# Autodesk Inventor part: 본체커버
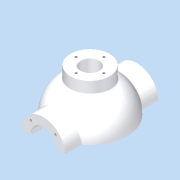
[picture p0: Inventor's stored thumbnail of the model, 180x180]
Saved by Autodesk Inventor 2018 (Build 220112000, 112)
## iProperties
Created: 2015-12
Part Number: 본체커버
Material: 알루미늄 6061
Document SubType Name: Modeling
Designer: mduedu
Density: 2.71 g/cm^3
Mass: 487.453 g
Surface Area: 431.319 cm^2
Volume: 179.872 cm^3
Appearance: 알루미늄 - 평지
Author: mduedu
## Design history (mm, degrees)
sketch "스케치1"
  geometry: L1 (-53, 0)-(53, 0); A1 r 53 centre (0, 0) between (53, 0) and (-53, 0); 2 further points
  constraints: 2 coincident, 2 end point, 2 point on circle, 1 centre point, 1 horizontal, 1 midpoint
  dimensions: "d0" = 53 radius of A1
revolve "회전1" sketch "스케치1" stored, may be unused: angle "d2" = 90 deg
feature "쉘1" dims "d11" = 8
node "작업 평면1"
sketch "스케치2"
  geometry: C1 r 31 at (0, 0); 1 further point
  constraints: 1 centre point, 1 coincident
  dimensions: "d4" = 62 diameter of C1
extrude "돌출1" join sketch "스케치2" stored distance "d5" = 10; taper "d6" = 0 deg
hole "구멍1" diameter "d14" = 35; stored, may be unused: countersink angle "d18" = 90 deg, drill point angle "d20" = 0 deg; dims "d12" = 10, "d13" = 10, "d15" = 6, "d16" = 4, "d17" = 2, "d19" = 16
hole "구멍2" diameter "d23" = 27; stored, may be unused: countersink angle "d27" = 90 deg, drill point angle "d29" = 0 deg; dims "d21" = 10, "d22" = 10, "d24" = 6, "d25" = 4, "d26" = 2, "d28" = 16
fillet "모깎기1" dims "d30" = 0.3
chamfer "모따기1" distance "d40" = 1; stored, may be unused: second distance "d41" = 2, angle "d42" = 45 deg
sketch "스케치4"
  geometry: L1 (0, 0)-(0, -25); L2 (0, 0)-(-17.678, -17.678); A1 r 25 centre (0, 0) between (-17.678, -17.678) and (0, -25); 1 further point
  constraints: 4 end point, 2 point on circle, 1 centre point, 1 coincident, 1 vertical
  dimensions: "d43" = 50 diameter of A1; "d47" = 45 deg angle of L1 L2
hole "구멍4" sketch "스케치4" at (-17.678, -17.678) diameter "d49" = 3.242; stored, may be unused: countersink angle "d53" = 90 deg, drill point angle "d55" = 118 deg; dims "d50" = 11, "d51" = 4, "d52" = 2, "d54" = 13
node "작업 평면3"
sketch "스케치6"
  geometry: C1 r 65 at (0, 0); 1 further point
  constraints: 1 centre point, 1 coincident
  dimensions: "d78" = 130 diameter of C1
extrude "돌출3" join sketch "스케치6" distance "d80" = 10; taper "d81" = 0 deg
sketch "스케치7"
  geometry: C1 r 20 at (0, 0); 1 further point
  constraints: 1 centre point, 1 coincident
  dimensions: "d82" = 40 diameter of C1
extrude "돌출4" join sketch "스케치7" stored distance "d84" = 10; taper "d85" = 0 deg
sketch "스케치8"
  geometry: 2 further points
  constraints: 1 coincident
hole "구멍6" sketch "스케치8" at (0, 0) diameter "d86" = 20; stored, may be unused: countersink angle "d90" = 90 deg, drill point angle "d92" = 118 deg; dims "d87" = 7, "d88" = 40, "d89" = 5, "d91" = 10
fillet "모깎기2" dims "d93" = 0.3
sketch "스케치9"
  geometry: L1 (65, -75)-(-65, -75) reference; L2 (-45, -75)-(-38.245, -36.692); A1 r 53 centre (0, 0) between (42.988, 31) and (42.988, -31) reference; 1 further point
  constraints: 2 end point, 1 point on circle, 1 point on line
  dimensions: "d94" = 45 horizontal distance of L2.start point (0, 0); "d95" = 80 deg angle of L2 L1
feature "리브1" sketch "스케치9" dims "d96" = 1, "d97" = 8, "d98" = 0, "d99" = 0, "d100" = 1, "d101" = 1
sketch "스케치10"
  geometry: L1 (0, 0)-(0, -55); L2 (0, 0)-(-38.891, -38.891); A1 r 55 centre (0, 0) between (0, -55) and (-38.891, -38.891); 2 further points
  constraints: 4 end point, 2 coincident, 2 point on circle, 1 centre point, 1 vertical
  dimensions: "d105" = 110 diameter of A1; "d107" = 45 deg angle of L1 L2
hole "구멍7" sketch "스케치10" at (-38.891, -38.891) diameter "d109" = 10; stored, may be unused: countersink angle "d113" = 90 deg, drill point angle "d115" = 118 deg; dims "d110" = 7, "d111" = 40, "d112" = 5, "d114" = 10
fillet "모깎기3" dims "d120" = 3
fillet "모깎기4" dims "d121" = 3, "d122" = 3
fillet "모깎기5" dims "d123" = 3
fillet "모깎기6" dims "d124" = 3
sketch "스케치11"
  geometry: C1 r 5 at (-38.891, 38.891) reference; C2 r 5 at (38.891, 38.891) reference; C3 r 5 at (38.891, -38.891) reference; C4 r 5 at (-38.891, -38.891) reference; C5 r 20 at (0, 0) reference; C6 r 65 at (0, 0) reference; 1 further point
  constraints: 3 other
feature "엠보싱1" sketch "스케치11" dims "d125" = 0.5, "d126" = 0
sketch "스케치12"
  geometry: L1 (0, 100)-(0, -100); L2 (0, 100)-(-150, 100); L3 (-150, 100)-(-150, -100); L4 (-150, -100)-(0, -100); 2 further points
  constraints: 8 end point, 3 perpendicular, 1 coincident, 1 midpoint, 1 vertical
  dimensions: "d127" = 200 distance of L2.end L3.end; "d129" = 150 distance of L3.end L1.end
extrude "돌출5" cut sketch "스케치12" extent not by distance; stored distance "d130" = 10; taper "d131" = 0 deg
node "작업 평면4"
sketch "스케치16"
  geometry: C1 r 28 at (0, 0); 1 further point
  constraints: 1 centre point, 1 coincident
  dimensions: "d148" = 56 diameter of C1
extrude "돌출9" join sketch "스케치16" stored distance "d150" = 5; taper "d151" = 0 deg
hole "구멍8" diameter "d154" = 26; stored, may be unused: countersink angle "d158" = 90 deg, drill point angle "d160" = 118 deg; dims "d152" = 10, "d153" = 10, "d155" = 6, "d156" = 4, "d157" = 2, "d159" = 8
sketch "스케치17" dims "d161" = 40
  geometry: 3 further points
  constraints: 2 vertical alignment, 1 coincident, 2 other
hole "구멍9" sketch "스케치17" at (0, 20) diameter "d163" = 3.242; stored, may be unused: countersink angle "d167" = 90 deg, drill point angle "d169" = 118 deg; dims "d164" = 8, "d165" = 4, "d166" = 2, "d168" = 10
fillet "모깎기11" dims "d173" = 3
chamfer "모따기2" distance "d174" = 1; stored, may be unused: second distance "d175" = 2, angle "d176" = 45 deg
node "솔리드1"
mirror "대칭1"
mirror "대칭2"
pattern_circular "원형 패턴1" dims angle "d57" = 360 deg
mirror "대칭3"
pattern_circular "원형 패턴3" dims angle "d103" = 360 deg
pattern_circular "원형 패턴4" dims angle "d118" = 360 deg
pattern_circular "원형 패턴5" dims angle "d171" = 360 deg
node "투영된 루프1"
other parameters: "d3" = 67, "d77" = -85, "d147" = 62
